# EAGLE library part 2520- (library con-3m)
3M (TM) Pak 100 4-Wall Header Source: 3M
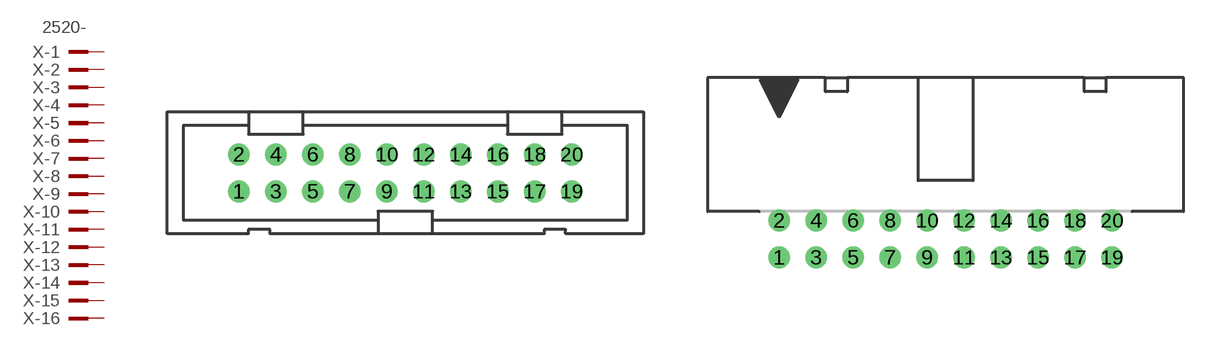
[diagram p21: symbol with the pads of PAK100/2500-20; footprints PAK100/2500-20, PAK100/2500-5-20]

Designator prefix X; gates -1=PINV -2=PIN -3=PIN -4=PIN -5=PIN -6=PIN -7=PIN -8=PIN -9=PIN -10=PIN -11=PIN -12=PIN -13=PIN -14=PIN -15=PIN -16=PIN -17=PIN -18=PIN -19=PIN -20=PIN

## 2520- (OC_FARNELL: unknown; OC_NEWARK: unknown)  [PAK100/2500-20]
1  -1:KL  pas
2  -2:KL  pas
3  -3:KL  pas
4  -4:KL  pas
5  -5:KL  pas
6  -6:KL  pas
7  -7:KL  pas
8  -8:KL  pas
9  -9:KL  pas
10  -10:KL  pas
11  -11:KL  pas
12  -12:KL  pas
13  -13:KL  pas
14  -14:KL  pas
15  -15:KL  pas
16  -16:KL  pas
17  -17:KL  pas
18  -18:KL  pas
19  -19:KL  pas
20  -20:KL  pas

## 2520-5 (MPN: D2520-5002-AR; OC_FARNELL: unknown; OC_NEWARK: 12P7058)  [PAK100/2500-5-20]
Pads as for PAK100/2500-20

## Footprint PAK100/2500-20 (pad centres in mm)
3M (TM) Pak 100 4-Wall Header Straight Source: 3M
drill 1 pad 1.422 round: 1 -11.43,-1.27; 2 -11.43,1.27; 3 -8.89,-1.27; 4 -8.89,1.27; 5 -6.35,-1.27; 6 -6.35,1.27; 7 -3.81,-1.27; 8 -3.81,1.27; 9 -1.27,-1.27; 10 -1.27,1.27; 11 1.27,-1.27; 12 1.27,1.27; 13 3.81,-1.27; 14 3.81,1.27; 15 6.35,-1.27; 16 6.35,1.27; 17 8.89,-1.27; 18 8.89,1.27; 19 11.43,-1.27; 20 11.43,1.27

## Footprint PAK100/2500-5-20 (pad centres in mm)
3M (TM) Pak 100 4-Wall Header Right Angle Source: 3M
drill 1 pad 1.422 round: 1 -11.43,-1.27; 2 -11.43,1.27; 3 -8.89,-1.27; 4 -8.89,1.27; 5 -6.35,-1.27; 6 -6.35,1.27; 7 -3.81,-1.27; 8 -3.81,1.27; 9 -1.27,-1.27; 10 -1.27,1.27; 11 1.27,-1.27; 12 1.27,1.27; 13 3.81,-1.27; 14 3.81,1.27; 15 6.35,-1.27; 16 6.35,1.27; 17 8.89,-1.27; 18 8.89,1.27; 19 11.43,-1.27; 20 11.43,1.27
